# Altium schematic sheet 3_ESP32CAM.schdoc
size 165 x 101 mm
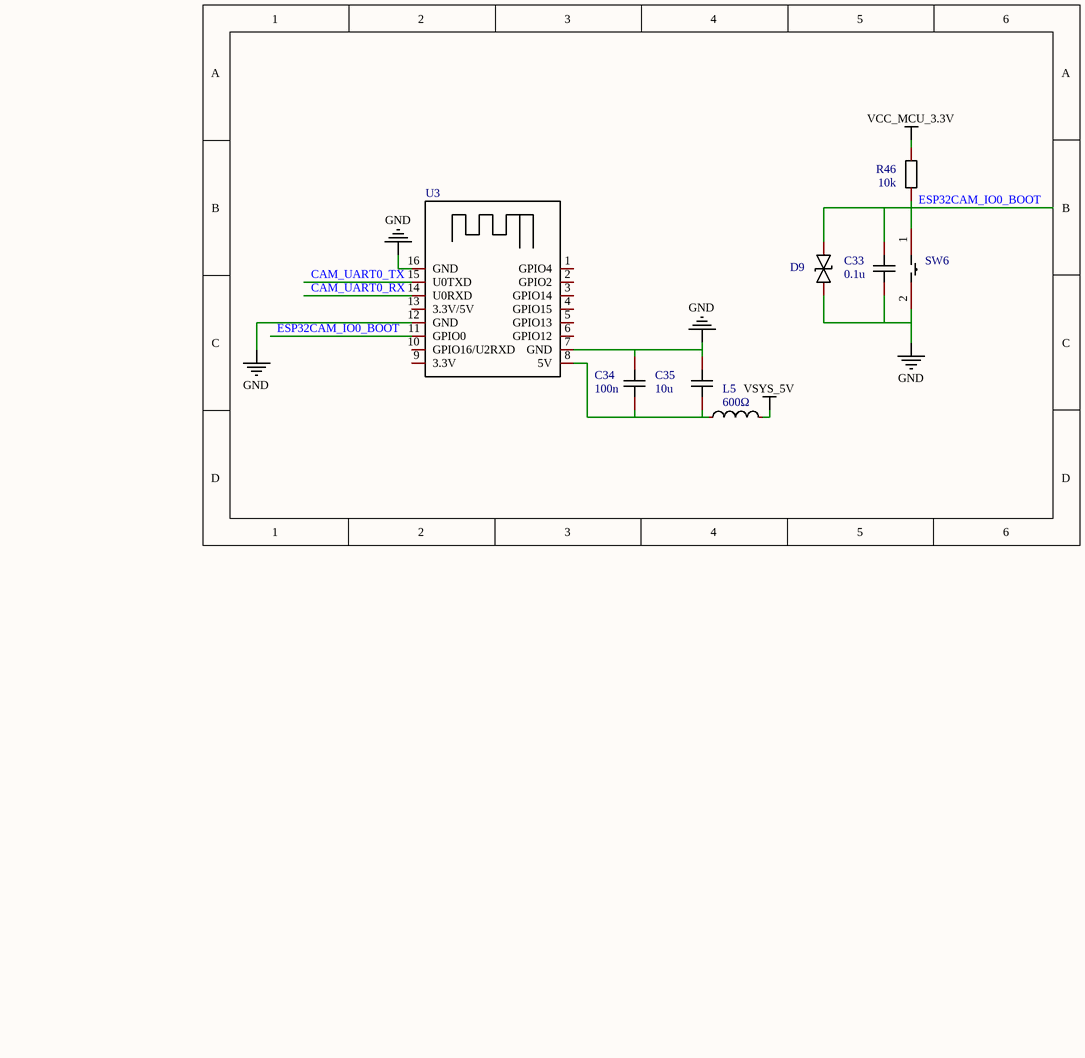
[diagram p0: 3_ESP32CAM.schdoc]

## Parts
C33  0.1u  [C0603]
C34  100n  [C0603]
C35  10u  [C0603]
D9  SD03C  [SOD-323_L1.8-W1.3-LS2.5-BI]  (value not drawn)
L5  600Ω  [L0603]
R46  10k  [R0603]
SW6  YTSA010A0252501B  [SW-SMD_L4.0-W3.0-LS5.0]  (value not drawn)
U3  MyLib_ESP32CAM  [ESP32CAM]  (value not drawn)

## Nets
GND: C33.1 C34.2 C35.2 D9.2 SW6.2 U3.7(GND) U3.12(GND) U3.16(GND)
VCC_MCU_3.3V: R46.2
VSYS_5V: L5.2
CAM_UART0_RX: U3.14(U0RXD)
CAM_UART0_TX: U3.15(U0TXD)
ESP32CAM_IO0_BOOT: C33.2 D9.1 R46.1 SW6.1 U3.11(GPIO0)
NetC34_1: C34.1 C35.1 L5.1 U3.8(5V)

Not connected (* = marked no-connect by the designer): U3 1(GPIO4) 2(GPIO2) 3(GPIO14) 4(GPIO15) 5(GPIO13) 6(GPIO12) 9(3.3V) 10(GPIO16/U2RXD) 13(3.3V/5V)

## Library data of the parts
C33-C35 = CAP_0603: Symbol: CapAcitance; Convert to PCB: yes
D9 = SD03C_C502532: 极性:双向;反向截止电压(Vrwm):3.3V;击穿电压(最小值):4V;峰值脉冲电流(Ipp)@10/1000μs:20A;最大钳位电压:16V;; Manufacturer: MDD; Add into BOM: yes; Polarity: 双向; Reverse Stand-Off Voltage (Vrwm): 3.3V; Breakdown Voltage (Min): 4V; Peak Pulse Current (Ipp)@10/1000μs: 20A; Maximum Clamping Voltage: 16V
L5 = L_0603: Symbol: SDFL1608S100KTF; Add into BOM: yes
R46 = AECR0603F1K50K9: Manufacturer: RESI(开步睿思）; Add into BOM: yes; Tolerance: ±1%; Power(Watts): 100mW; Temperature Coefficient: ±100ppm/℃; Overload Voltage (Max): 50V; Description: 电阻类型:厚膜电阻;阻值:1.5kΩ;精度:±1%;功率:100mW;温度系数:±100ppm/℃;最大工作电压:50V;工作温度范围:-55℃~+125℃;
SW6 = YTSA010A0252501B: 触点电流:50mA;额定电压(DC):12V;绝缘电阻:100MΩ;电路结构:单刀单掷;安装方式:立贴;按钮形状:圆形按钮;按钮/盖帽颜色:黑色;作用力:250gf;机械寿命:50000;引脚样式:SMD接片;开关长度:4mm;开关宽度:3mm;开关高度:2.5mm;带支架:否;; Manufacturer: DGBZ(东莞博众); Add into BOM: yes; Contact Current: 50mA; Voltage Rating (DC): 12V; Insulation Resistance: 100MΩ; Circuit: 单刀单掷; Actuator Style: 圆形按钮; Actuator/Cap Color: 黑色; Operating Force: 250gf; Mechanical Life: 50000; Pin Style: SMD接片; Switch Length: 4mm; Switch Width: 3mm; Switch Height: 2.5mm; Strike Gundam: 否
U3 = ESP32CAM: Pin Type: IN; Add into BOM: yes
